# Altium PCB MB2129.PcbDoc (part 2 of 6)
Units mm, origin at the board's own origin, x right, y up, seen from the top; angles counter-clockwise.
Board outline 70 x 133.34 mm, 6 copper layers (Top Layer, Signal Layer 1, Signal Layer 2, Signal Layer 3, Signal Layer 4, Bottom Layer), stack 1.57 mm thick; 377 components, 289 nets, 1482 pads, 1373 vias.
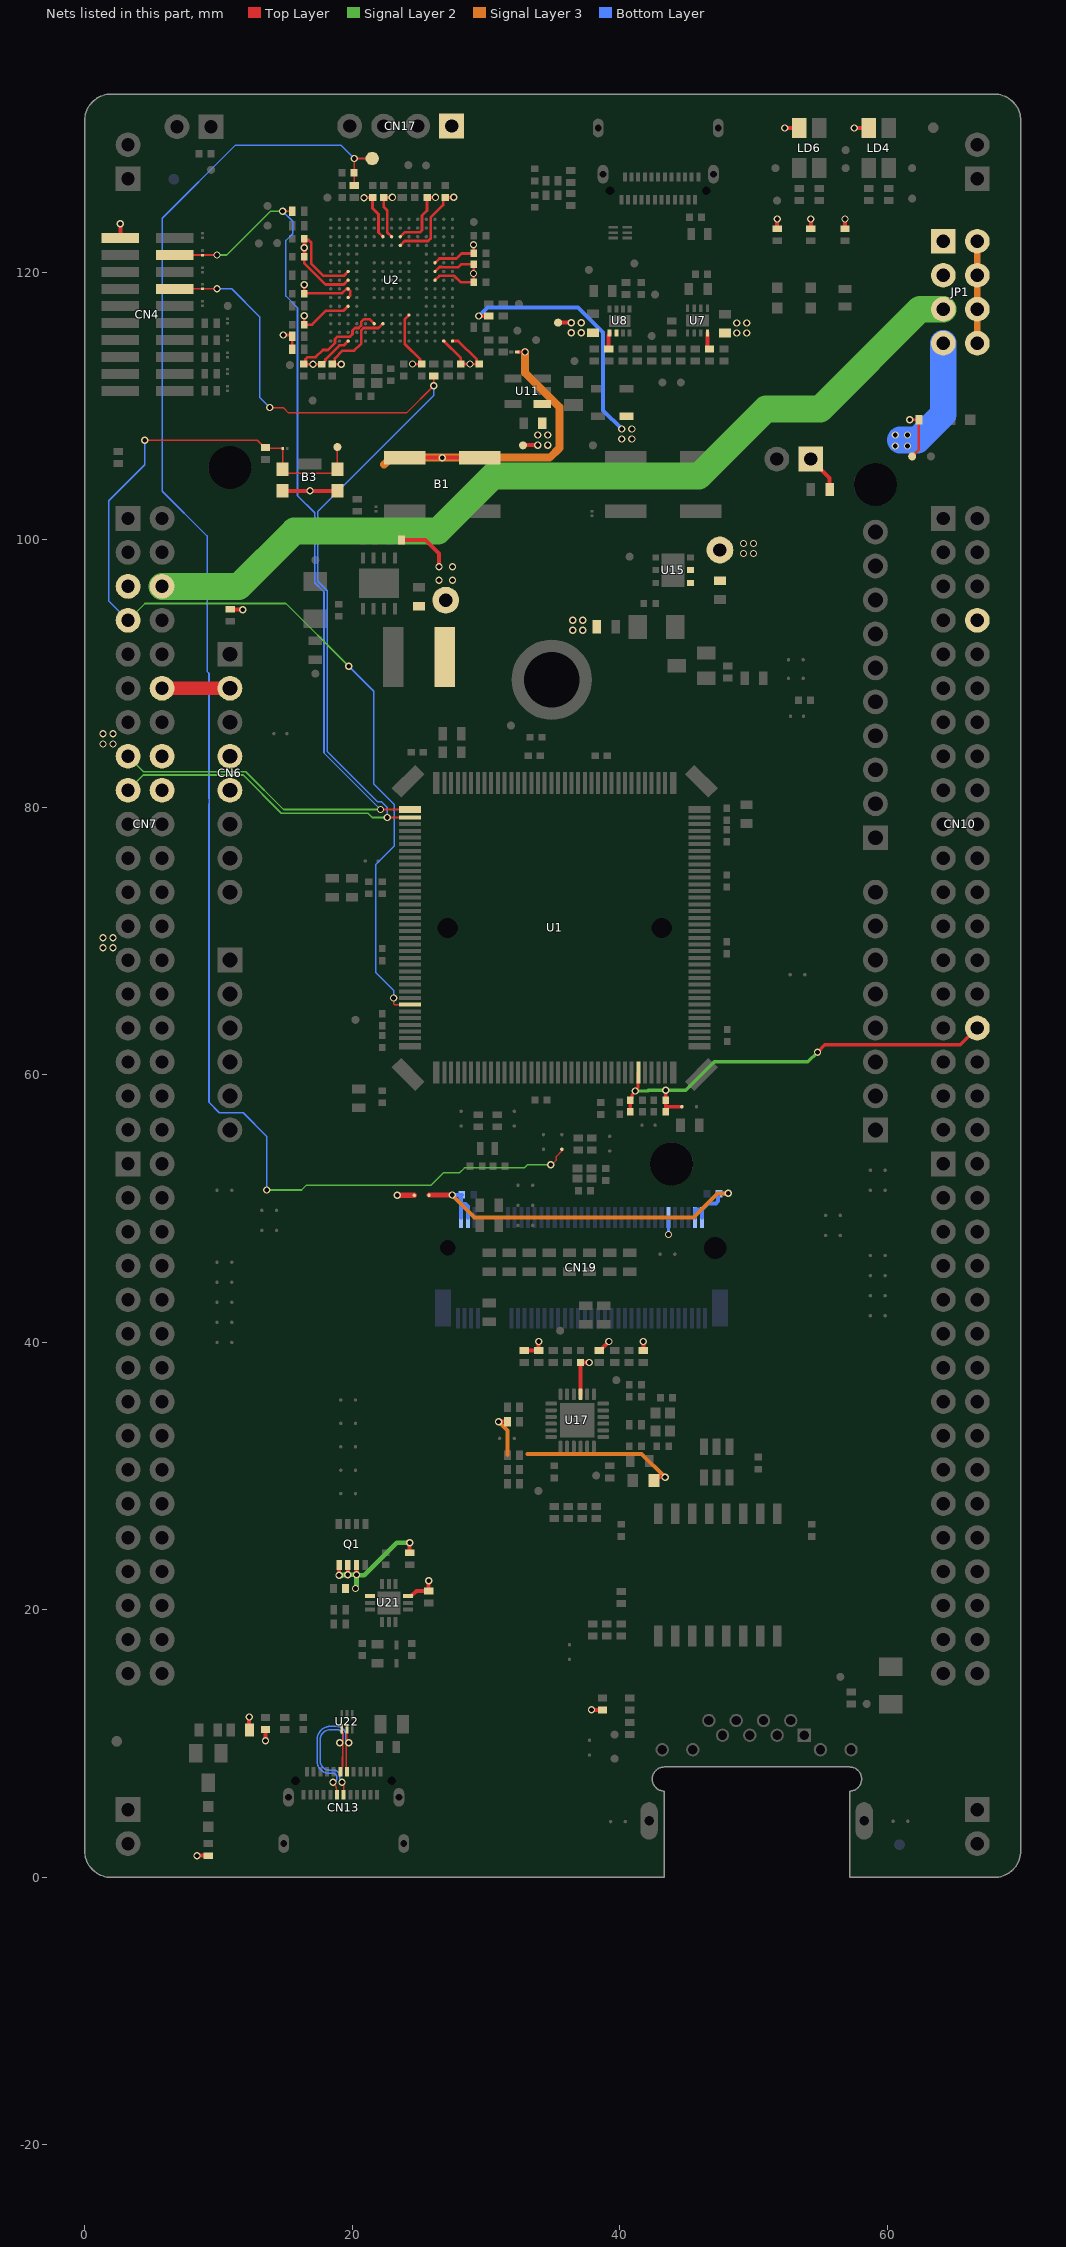
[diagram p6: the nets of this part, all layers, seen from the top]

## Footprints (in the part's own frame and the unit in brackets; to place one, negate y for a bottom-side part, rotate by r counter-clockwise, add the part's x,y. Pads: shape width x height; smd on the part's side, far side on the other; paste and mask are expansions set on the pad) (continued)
CON_SAMTEC_TSW-119-09-X-D [mm]
  rect 1.85x1.85 / inner round 1.85 / far side rect 1.85x1.85 hole 1 mask+0.05: 1(-22.86,-1.27)
  round 1.85 hole 1 mask+0.05: 2(-22.86,1.27) 3(-20.32,-1.27) 4(-20.32,1.27) 5(-17.78,-1.27) 6(-17.78,1.27) 7(-15.24,-1.27) 8(-15.24,1.27) 9(-12.7,-1.27) 10(-12.7,1.27) 11(-10.16,-1.27) 12(-10.16,1.27) 13(-7.62,-1.27) 14(-7.62,1.27) 15(-5.08,-1.27) 16(-5.08,1.27) 17(-2.54,-1.27) 18(-2.54,1.27) 19(0,-1.27) 20(0,1.27) 21(2.54,-1.27) 22(2.54,1.27) 23(5.08,-1.27) 24(5.08,1.27) 25(7.62,-1.27) 26(7.62,1.27) 27(10.16,-1.27) 28(10.16,1.27) 29(12.7,-1.27) 30(12.7,1.27) 31(15.24,-1.27) 32(15.24,1.27) 33(17.78,-1.27) 34(17.78,1.27) 35(20.32,-1.27) 36(20.32,1.27) 37(22.86,-1.27) 38(22.86,1.27)
  silkscreen extent -24.13,-2.54 24.13,2.54, body extent -24.13,-2.55 24.13,2.54, height 8.38
CON_USB-TYPEC_AMPHENOL_12401826E412A [mm] "MCD-03232"
  round 0 hole 0.65 unplated mask+0.05: 0(-3.6,0)
  round 0 hole 0.65 slot 0.95 at 0 deg unplated mask+0.05: 0(3.6,0)
  rect 0.3x0.7 smd mask+0.05: A1(-2.75,0.66) A2(-2.25,0.66) A3(-1.75,0.66) A4(-1.25,0.66) A5(-0.75,0.66) A6(-0.25,0.66) A7(0.25,0.66) A8(0.75,0.66) A9(1.25,0.66) A10(1.75,0.66) A11(2.25,0.66) A12(2.75,0.66) B1(2.5,-1.04) B2(2,-1.04) B3(1.5,-1.04) B4(1,-1.04) B5(0.5,-1.04) B6(0,-1.04) B7(-0.5,-1.04) B8(-1,-1.04) B9(-1.5,-1.04) B10(-2,-1.04) B11(-2.5,-1.04) B12(-3,-1.04)
  oval 0.8x1.4 hole 0.5 slot 1.1 at 90 deg mask+0.05: SH1(-4.13,-1.25) SH2(4.13,-1.25) SH3(-4.49,-4.7) SH4(4.49,-4.7)
  Top Layer keep-out region: -3.75,-7.24 3.75,-7.24 3.75,-1.95 -3.75,-1.95
  silkscreen extent -4.7,-9.59 4.7,0.91, body extent -4.6,-9.59 4.6,0.91, height 3.26
CRY_NX1610SE_2P [mm] "MCD-02291"
  rect 0.5x1 smd mask+0.05: 1(-0.55,0) 2(0.55,0)
  silkscreen extent -0.13,-0.5 0.13,0.5, body extent -0.8,-0.5 0.8,0.5, height 0.45
CRY_NX1612SA_4P [mm] "MCD-02262"
  rect 0.75x0.6 smd mask+0.038: 1(-0.525,-0.375) 2(0.525,-0.375) 3(0.525,0.375) 4(-0.525,0.375)
  silkscreen extent -1.02,-0.8 0.03,0.6, body extent -0.8,-0.6 0.8,0.6, height 0.31
CRY_NX2016SA_4P [mm]
  rect 0.85x0.75 smd mask+0.05: 1(-0.675,-0.525) 2(0.675,-0.525) 3(0.675,0.525) 4(-0.675,0.525)
  silkscreen extent -1.22,-1.02 1.05,0.85, body extent -1.05,-0.85 1.05,0.85, height 0.7
DIO_SOD323_1A_2K [mm]
  rect 1.06x0.54 smd mask+0.05: 1(-1.07,0) 2(1.07,0)
  silkscreen extent -0.9,-0.72 0.9,0.72, body extent -1.3,-0.78 1.3,0.78, height 1.17
DIO_SOD523_1A_2K [mm] "MCD-01677"
  rect 0.65x0.3 smd mask+0.05: 1(-0.675,0) 2(0.675,0)
  silkscreen extent -0.65,-0.45 1.05,0.55, body extent -0.85,-0.45 0.85,0.45, height 0.71
ESD_0201_H0P3_1K_2A [mm] "MCD-03501"
  rect 0.187x0.225 smd paste-0.01 mask+0.025: 1(-0.169,0) 2(0.169,0)
  silkscreen extent -0.35,-0.15 -0.35,0.15, body extent -0.3,-0.17 0.3,0.17, height 0.3
ESD_QFN1610_2N_1K_2A [mm] "DFN, 2-Leads, Body 1.60x1.00mm"
  rect 0.55x0.9 smd mask+0.05: 1(-0.625,0) 2(0.625,0)
  silkscreen extent -1.02,-0.58 0.85,0.58, body extent -0.85,-0.55 0.85,0.55, height 0.6
ESD_SOT23-6L [mm]
  rect 0.6x1.2 smd mask+0.05: 1(-0.95,-1.15) 2(0,-1.15) 3(0.95,-1.15) 4(0.95,1.15) 5(0,1.15) 6(-0.95,1.15)
  silkscreen extent -1.53,-0.87 1.53,0.87, body extent -1.52,-1.5 1.52,1.5, height 1.45
ESD_UQFN-6L_1P45X1P4_P040 [mm] "MCD-03060"
  rect 0.2x0.7 smd mask+0.05: 1(-0.4,-0.525) 2(0,-0.525) 3(0.4,-0.525) 4(0.4,0.525) 5(0,0.525) 6(-0.4,0.525)
  body extent -0.72,-0.7 0.72,0.7, height 0.51
ICC_DFN6-EPAD_3X3_P095 [mm]
  rect 0.45x0.5 smd mask+0.05: 1(-0.95,-1.3) 2(0,-1.3) 3(0.95,-1.3) 4(0.95,1.3) 5(0,1.3) 6(-0.95,1.3)
  rect 2.5x1.7 smd mask+0.05: EP(0,0)
  silkscreen extent -1.55,-1.55 1.55,1.55, body extent -1.55,-1.55 1.55,1.55, height 1
ICC_DFN8-EPAD_2X2_P050_H0P8 [mm] "MCD-03814"
  rect 0.25x0.55 smd mask+0.05: 1(0.75,0.925) 2(0.25,0.925) 3(-0.25,0.925) 4(-0.75,0.925) 5(-0.75,-0.925) 6(-0.25,-0.925) 7(0.25,-0.925) 8(0.75,-0.925)
  rect 1.75x0.9 smd mask+0.05: 9(0,0)
  silkscreen extent -1.05,-1.05 1.25,1.35, body extent -1,-1.05 1,1.05, height 0.8
ICC_LQFP144_20X20_P050_SOCKET_YAMAICHI_IC149-144-145-B5_NM [mm]
  rect 1x2.5 smd rot 45 mask+0.05: 0(-10.96,-10.96) 0(10.96,10.96)
  rect 1x2.5 smd rot 135 mask+0.05: 0(-10.96,10.96) 0(10.96,-10.96)
  round 0 hole 1.5 unplated mask+0.05: 0(0,8) 0(0,-8)
  rect 1.65x0.5 smd mask+0.05: 1(-10.825,8.85) 36(-10.825,-8.85) 73(10.825,-8.85) 108(10.825,8.85)
  rect 1.65x0.3 smd mask+0.05: 2(-10.825,8.25) 3(-10.825,7.75) 4(-10.825,7.25) 5(-10.825,6.75) 6(-10.825,6.25) 7(-10.825,5.75) 8(-10.825,5.25) 9(-10.825,4.75) 10(-10.825,4.25) 11(-10.825,3.75) 12(-10.825,3.25) 13(-10.825,2.75) 14(-10.825,2.25) 15(-10.825,1.75) 16(-10.825,1.25) 17(-10.825,0.75) 18(-10.825,0.25) 19(-10.825,-0.25) 20(-10.825,-0.75) 21(-10.825,-1.25) 22(-10.825,-1.75) 23(-10.825,-2.25) 24(-10.825,-2.75) 25(-10.825,-3.25) 26(-10.825,-3.75) 27(-10.825,-4.25) 28(-10.825,-4.75) 29(-10.825,-5.25) 30(-10.825,-5.75) 31(-10.825,-6.25) 32(-10.825,-6.75) 33(-10.825,-7.25) 34(-10.825,-7.75) 35(-10.825,-8.25) 74(10.825,-8.25) 75(10.825,-7.75) 76(10.825,-7.25) 77(10.825,-6.75) 78(10.825,-6.25) 79(10.825,-5.75) 80(10.825,-5.25) 81(10.825,-4.75) 82(10.825,-4.25) 83(10.825,-3.75) 84(10.825,-3.25) 85(10.825,-2.75) 86(10.825,-2.25) 87(10.825,-1.75) 88(10.825,-1.25) 89(10.825,-0.75) 90(10.825,-0.25) 91(10.825,0.25) 92(10.825,0.75) 93(10.825,1.25) 94(10.825,1.75) 95(10.825,2.25) 96(10.825,2.75) 97(10.825,3.25) 98(10.825,3.75) 99(10.825,4.25) 100(10.825,4.75) 101(10.825,5.25) 102(10.825,5.75) 103(10.825,6.25) 104(10.825,6.75) 105(10.825,7.25) 106(10.825,7.75) 107(10.825,8.25)
  rect 0.5x1.65 smd mask+0.05: 37(-8.85,-10.825) 72(8.85,-10.825) 109(8.85,10.825) 144(-8.85,10.825)
  rect 0.3x1.65 smd mask+0.05: 38(-8.25,-10.825) 39(-7.75,-10.825) 40(-7.25,-10.825) 41(-6.75,-10.825) 42(-6.25,-10.825) 43(-5.75,-10.825) 44(-5.25,-10.825) 45(-4.75,-10.825) 46(-4.25,-10.825) 47(-3.75,-10.825) 48(-3.25,-10.825) 49(-2.75,-10.825) 50(-2.25,-10.825) 51(-1.75,-10.825) 52(-1.25,-10.825) 53(-0.75,-10.825) 54(-0.25,-10.825) 55(0.25,-10.825) 56(0.75,-10.825) 57(1.25,-10.825) 58(1.75,-10.825) 59(2.25,-10.825) 60(2.75,-10.825) 61(3.25,-10.825) 62(3.75,-10.825) 63(4.25,-10.825) 64(4.75,-10.825) 65(5.25,-10.825) 66(5.75,-10.825) 67(6.25,-10.825) 68(6.75,-10.825) 69(7.25,-10.825) 70(7.75,-10.825) 71(8.25,-10.825) 110(8.25,10.825) 111(7.75,10.825) 112(7.25,10.825) 113(6.75,10.825) 114(6.25,10.825) 115(5.75,10.825) 116(5.25,10.825) 117(4.75,10.825) 118(4.25,10.825) 119(3.75,10.825) 120(3.25,10.825) 121(2.75,10.825) 122(2.25,10.825) 123(1.75,10.825) 124(1.25,10.825) 125(0.75,10.825) 126(0.25,10.825) 127(-0.25,10.825) 128(-0.75,10.825) 129(-1.25,10.825) 130(-1.75,10.825) 131(-2.25,10.825) 132(-2.75,10.825) 133(-3.25,10.825) 134(-3.75,10.825) 135(-4.25,10.825) 136(-4.75,10.825) 137(-5.25,10.825) 138(-5.75,10.825) 139(-6.25,10.825) 140(-6.75,10.825) 141(-7.25,10.825) 142(-7.75,10.825) 143(-8.25,10.825)
  silkscreen extent -10.1,-10.1 10.1,10.1, body extent -11,-11 11,11, height 1.6
ICC_QFN12L-EPAD_3X3_P050 [mm] "MCD-01809"
  rect 0.3x0.75 smd mask+0.05: 1(-0.5,-1.425) 2(0,-1.425) 3(0.5,-1.425) 7(0.5,1.425) 8(0,1.425) 9(-0.5,1.425)
  rect 0.75x0.3 smd mask+0.05: 4(1.425,-0.5) 5(1.425,0) 6(1.425,0.5) 10(-1.425,0.5) 11(-1.425,0) 12(-1.425,-0.5)
  rect 1.7x1.7 smd mask+0.05: 13(0,0)
  body extent -1.55,-1.55 1.55,1.55, height 0.8
ICC_SOT23-3L_H1P12 [mm]
  rect 1x1.4 smd mask+0.05: 1(-0.95,-1.1) 2(0.95,-1.1) 3(0,1.1)
  silkscreen extent -1.63,-0.82 1.63,0.82, body extent -1.56,-1.25 1.56,1.25, height 1.12
ICC_SOT23-5L_H1P45 [mm]
  rect 0.6x1.3 smd mask+0.05: 1(-0.95,-1.1) 2(0,-1.1) 3(0.95,-1.1) 4(0.95,1.1) 5(-0.95,1.1)
  silkscreen extent -1.75,-1.68 1.6,0.97, body extent -1.52,-1.25 1.52,1.25, height 1.45
ICC_UFBGA201_176+25_10X10_P065 [mm] "IPC"
  round 0.25 smd mask+0.038: A1(-4.55,4.55) A2(-3.9,4.55) A3(-3.25,4.55) A4(-2.6,4.55) A5(-1.95,4.55) A6(-1.3,4.55) A7(-0.65,4.55) A8(0,4.55) A9(0.65,4.55) A10(1.3,4.55) A11(1.95,4.55) A12(2.6,4.55) A13(3.25,4.55) A14(3.9,4.55) A15(4.55,4.55) B1(-4.55,3.9) B2(-3.9,3.9) B3(-3.25,3.9) B4(-2.6,3.9) B5(-1.95,3.9) B6(-1.3,3.9) B7(-0.65,3.9) B8(0,3.9) B9(0.65,3.9) B10(1.3,3.9) B11(1.95,3.9) B12(2.6,3.9) B13(3.25,3.9) B14(3.9,3.9) B15(4.55,3.9) C1(-4.55,3.25) C2(-3.9,3.25) C3(-3.25,3.25) C4(-2.6,3.25) C5(-1.95,3.25) C6(-1.3,3.25) C7(-0.65,3.25) C8(0,3.25) C9(0.65,3.25) C10(1.3,3.25) C11(1.95,3.25) C12(2.6,3.25) C13(3.25,3.25) C14(3.9,3.25) C15(4.55,3.25) D1(-4.55,2.6) D2(-3.9,2.6) D3(-3.25,2.6) D4(-2.6,2.6) D5(-1.95,2.6) D6(-1.3,2.6) D7(-0.65,2.6) D8(0,2.6) D9(0.65,2.6) D10(1.3,2.6) D11(1.95,2.6) D12(2.6,2.6) D13(3.25,2.6) D14(3.9,2.6) D15(4.55,2.6) E1(-4.55,1.95) E2(-3.9,1.95) E3(-3.25,1.95) E4(-2.6,1.95) E12(2.6,1.95) E13(3.25,1.95) E14(3.9,1.95) E15(4.55,1.95) F1(-4.55,1.3) F2(-3.9,1.3) F3(-3.25,1.3) F4(-2.6,1.3) F6(-1.3,1.3) F7(-0.65,1.3) F8(0,1.3) F9(0.65,1.3) F10(1.3,1.3) F12(2.6,1.3) F13(3.25,1.3) F14(3.9,1.3) F15(4.55,1.3) G1(-4.55,0.65) G2(-3.9,0.65) G3(-3.25,0.65) G4(-2.6,0.65) G6(-1.3,0.65) G7(-0.65,0.65) G8(0,0.65) G9(0.65,0.65) G10(1.3,0.65) G12(2.6,0.65) G13(3.25,0.65) G14(3.9,0.65) G15(4.55,0.65) H1(-4.55,0) H2(-3.9,0) H3(-3.25,0) H4(-2.6,0) H6(-1.3,0) H7(-0.65,0) H8(0,0) H9(0.65,0) H10(1.3,0) H12(2.6,0) H13(3.25,0) H14(3.9,0) H15(4.55,0) J1(-4.55,-0.65) J2(-3.9,-0.65) J3(-3.25,-0.65) J4(-2.6,-0.65) J6(-1.3,-0.65) J7(-0.65,-0.65) J8(0,-0.65) J9(0.65,-0.65) J10(1.3,-0.65) J12(2.6,-0.65) J13(3.25,-0.65) J14(3.9,-0.65) J15(4.55,-0.65) K1(-4.55,-1.3) K2(-3.9,-1.3) K3(-3.25,-1.3) K4(-2.6,-1.3) K6(-1.3,-1.3) K7(-0.65,-1.3) K8(0,-1.3) K9(0.65,-1.3) K10(1.3,-1.3) K12(2.6,-1.3) K13(3.25,-1.3) K14(3.9,-1.3) K15(4.55,-1.3) L1(-4.55,-1.95) L2(-3.9,-1.95) L3(-3.25,-1.95) L4(-2.6,-1.95) L12(2.6,-1.95) L13(3.25,-1.95) L14(3.9,-1.95) L15(4.55,-1.95) M1(-4.55,-2.6) M2(-3.9,-2.6) M3(-3.25,-2.6) M4(-2.6,-2.6) M5(-1.95,-2.6) M6(-1.3,-2.6) M7(-0.65,-2.6) M8(0,-2.6) M9(0.65,-2.6) M10(1.3,-2.6) M11(1.95,-2.6) M12(2.6,-2.6) M13(3.25,-2.6) M14(3.9,-2.6) M15(4.55,-2.6) N1(-4.55,-3.25) N2(-3.9,-3.25) N3(-3.25,-3.25) N4(-2.6,-3.25) N5(-1.95,-3.25) N6(-1.3,-3.25) N7(-0.65,-3.25) N8(0,-3.25) N9(0.65,-3.25) N10(1.3,-3.25) N11(1.95,-3.25) N12(2.6,-3.25) N13(3.25,-3.25) N14(3.9,-3.25) N15(4.55,-3.25) P1(-4.55,-3.9) P2(-3.9,-3.9) P3(-3.25,-3.9) P4(-2.6,-3.9) P5(-1.95,-3.9) P6(-1.3,-3.9) P7(-0.65,-3.9) P8(0,-3.9) P9(0.65,-3.9) P10(1.3,-3.9) P11(1.95,-3.9) P12(2.6,-3.9) P13(3.25,-3.9) P14(3.9,-3.9) P15(4.55,-3.9) R1(-4.55,-4.55) R2(-3.9,-4.55) R3(-3.25,-4.55) R4(-2.6,-4.55) R5(-1.95,-4.55) R6(-1.3,-4.55) R7(-0.65,-4.55) R8(0,-4.55) R9(0.65,-4.55) R10(1.3,-4.55) R11(1.95,-4.55) R12(2.6,-4.55) R13(3.25,-4.55) R14(3.9,-4.55) R15(4.55,-4.55)
  silkscreen extent -5.22,-5.07 5.07,5.23, body extent -5.07,-5.07 5.07,5.07, height 0.61
ICC_VFQFPN8-EPAD_4X4_P080 [mm] "MCD-02219"
  rect 0.3x0.85 smd mask+0.05: 1(-1.2,-1.9) 2(-0.4,-1.9) 3(0.4,-1.9) 4(1.2,-1.9) 5(1.2,1.9) 6(0.4,1.9) 7(-0.4,1.9) 8(-1.2,1.9)
  rect 3x2.2 smd mask+0.05: 9(0,0)
  silkscreen extent -2,-2 2,2, body extent -2,-2 2,2, height 1.1
ICC_VQFN24-EPAD_4X4_P050 [mm]
  rrect50% 0.85x0.3 smd mask+0.05: 1(-1.95,1.25) 2(-1.95,0.75) 3(-1.95,0.25) 4(-1.95,-0.25) 5(-1.95,-0.75) 6(-1.95,-1.25) 13(1.95,-1.25) 14(1.95,-0.75) 15(1.95,-0.25) 16(1.95,0.25) 17(1.95,0.75) 18(1.95,1.25)
  rrect50% 0.3x0.85 smd mask+0.05: 7(-1.25,-1.95) 8(-0.75,-1.95) 9(-0.25,-1.95) 10(0.25,-1.95) 11(0.75,-1.95) 12(1.25,-1.95) 19(1.25,1.95) 20(0.75,1.95) 21(0.25,1.95) 22(-0.25,1.95) 23(-0.75,1.95) 24(-1.25,1.95)
  rect 2.6x2.6 smd paste-10 mask+0.05: EP(0,0)
  silkscreen extent -2,-2 2,2, body extent -2.05,-2.05 2.05,2.05, height 1.1
ICC_WSON8-EPAD_2X2_P050 [mm] "MCD-02194"
  rect 0.5x0.3 smd paste+0 mask+0.05: 1(-0.9,0.75) 2(-0.9,0.25) 3(-0.9,-0.25) 4(-0.9,-0.75) 5(0.9,-0.75) 6(0.9,-0.25) 7(0.9,0.25) 8(0.9,0.75)
  rect 0.9x1.6 smd paste+0 mask+0.05: 9(0,0)
  silkscreen extent -0.5,-1 0.5,1, body extent -1,-1 1,1, height 0.81
IND_5040_WURTH_74404054033 [mm] "MCD-02220"
  rect 1.55x4.5 smd mask+0.05: 1(1.925,0) 2(-1.925,0)
  silkscreen extent -1.5,-2.5 1.5,2.5, body extent -2.6,-2.5 2.6,2.5, height 4
L0603 [mm]
  rect 0.8x0.95 smd mask+0.05: 1(-0.8,0) 2(0.8,0)
  silkscreen extent -1.33,-0.6 1.33,0.6, body extent -0.87,-0.47 0.87,0.47, height 0.95
LED_0603_OSRAM_LG-Q396-PS-35_GREEN_1A2K_H0P4 [mm]
  rect 0.8x0.8 smd mask+0.05: 1(-0.75,0) 2(0.75,0)
  silkscreen extent -0.85,-0.53 1.28,0.53, body extent -0.85,-0.45 0.85,0.45, height 0.6
LED_0603_RED [mm]
  rect 0.8x0.8 smd mask+0.05: 1(-0.75,0) 2(0.75,0)
  silkscreen extent -0.25,-0.4 1.25,0.4, body extent -0.8,-0.4 0.8,0.4, height 0.6
LED_0603_SMD-B_BLUE_H0P4 [mm]
  rect 0.6x1 smd mask+0.05: 1(-0.65,0) 2(0.65,0)
  silkscreen extent -0.23,-0.45 1.07,0.45, body extent -0.85,-0.45 0.85,0.45, height 0.5
LED_BI-GR_WE-150141SV73110 [mm] "MCD-02631"
  rect 1.1x1.5 smd mask+0.05: 1(-0.75,1.5) 2(0.75,1.5) 3(-0.75,-1.5) 4(0.75,-1.5)
  silkscreen extent -1.65,-1.85 1.5,1.7, body extent -1.5,-1.85 1.5,1.85, height 2.1
LINK200 [mm]
  rect 0.2x0.35 smd paste-10 mask+0.05: 1(0,-0.225) 2(0,0.225)
MIRE_PLACE_SMD_0P8MM [mm]
  round 0.8 smd paste-10 mask+0.2: 1(0,0)
  Top Layer keep-out circle w0.01: c0,0 r0.804
MISC_REGO_S001_00001_A42_R [mm] "MCD-03863"
  round 6 hole 4.15 mask+0.05: 1(0,0)
  silkscreen extent -3.27,-3.27 3.27,3.27, body extent -2.8,-2.8 2.8,2.8, height 2.5
MOS_POWERFLAT_3P3X3P3_P065 [mm] "MCD-01126"
  rect 0.4x0.75 smd mask+0.05: 1(-0.975,-1.525) 2(-0.325,-1.525) 3(0.325,-1.525) 4(0.975,-1.525) 6(0.325,1.525) 7(-0.325,1.525)
  rect 0.45x0.75 smd mask+0.05: 5(1,1.525) 8(-1,1.525)
  Top Layer region: -1.755,0.2 -1.755,-0.2 -1.225,-0.2 -1.225,-0.5 1.225,-0.5 1.225,-0.2 1.755,-0.2 1.755,0.2 1.225,0.2 1.225,1.9 -1.225,1.9 -1.225,0.2
  silkscreen extent -1.63,-1.55 1.63,1.55, body extent -1.75,-1.75 1.75,1.75, height 0.91
NPN_SOT23 [mm]
  rect 1x1.4 smd mask+0.05: 1(-0.95,-1.1) 2(0.95,-1.1) 3(0,1.1)
  silkscreen extent -1.63,-0.82 1.63,0.82, body extent -1.56,-1.25 1.56,1.25, height 1.1
R0402 [mm]
  rect 0.51x0.7 smd mask+0.05: 1(-0.45,0) 2(0.45,0)
  body extent -0.52,-0.3 0.52,0.3, height 0.4
R0603 [mm]
  rect 0.64x1 smd mask+0.05: 1(-0.7,0) 2(0.7,0)
  silkscreen extent -1.05,-0.58 1.05,0.58, body extent -0.9,-0.5 0.9,0.5, height 0.56
SOLDER-BRIDGE_R0402-0R [mil] "MCD-01619"
  round 10 smd paste-393.7: 1(-17.72,0) 2(20.67,0)
  Top Layer region: -30.51,-13.78 -30.51,13.78 -8.86,13.78 -2.95,0 -8.86,-13.78
  Top Layer region: 1.48,13.78 8.37,0 1.48,-13.78 30.51,-13.78 30.51,13.78
  silkscreen extent -33,-17 33,17, body extent -20,-12 20,12, height 14
SOLDER-BRIDGE_R0603-0R [mil]
  round 10 smd paste-393.7: 1(-19.68,0) 2(23.62,0)
  Top Layer region: -3.94,19.69 15.75,0 -3.94,-19.68 47.24,-19.68 47.24,19.69
  Top Layer region: -47.24,-19.68 -47.24,19.69 -17.72,19.69 1.97,0 -17.72,-19.68
  silkscreen extent -50,-23 50,23, body extent -36,-20 36,20, height 22
STICKER_PRODUCT_25X9 [mm] "Sticker to mention board CPN code"
  silkscreen extent -12.5,-4.5 12.5,4.5
SWI_C&K_KSC321JLFS_BLACK [mm] "MCD-01799"
  rect 3.1x1 smd mask+0.05: 1(-2.8,2) 2(2.8,2) 3(-2.8,-2) 4(2.8,-2)
  silkscreen extent -3.25,-3.25 3.25,3.25, body extent -3.4,-3.25 3.4,3.25, height 3.5
SWI_C&K_KSC721JLFS_BLUE [mm] "MCD-01800"
  rect 3.1x1 smd mask+0.05: 1(-2.8,2) 2(2.8,2) 3(-2.8,-2) 4(2.8,-2)
  silkscreen extent -3.25,-3.25 3.25,3.25, body extent -3.4,-3.25 3.4,3.25, height 4.3
SWI_C&K_Y78B23110FP__ITT_KMR231GLFS [mm] "MCD-00715"
  rect 0.9x1 smd mask+0.05: 1(2.05,0.8) 2(2.05,-0.8) 3(-2.05,0.8) 4(-2.05,-0.8)
  rect 1.7x0.8 smd mask+0.05: 5(0,1.2)
  silkscreen extent -2.05,-1.43 2.05,1.43, body extent -2.3,-1.5 2.3,1.5, height 2.1
TP_PTH_1MM_2MM [mm] "MCD-01506"
  round 2 hole 1 mask+0.05: 1(0,0)
  silkscreen extent -1.2,-1.2 1.2,1.2
TP_SMD_0-6MM [mm]
  round 0.6 smd paste-10 mask+0.05: 1(0,0)
  silkscreen extent -0.5,-0.5 0.5,0.5
TP_SMD_1MM [mm]
  round 1 smd paste-10 mask+0.05: 1(0,0)
  silkscreen extent -0.7,-0.7 0.7,0.7
TRS_DGKYD_KMS-1102NL [mm]
  rect 0.64x1.55 smd mask+0.05: 1(-4.445,-4.575) 2(-3.175,-4.575) 3(-1.905,-4.575) 4(-0.635,-4.575) 5(0.635,-4.575) 6(1.905,-4.575) 7(3.175,-4.575) 8(4.445,-4.575) 9(4.445,4.575) 10(3.175,4.575) 11(1.905,4.575) 12(0.635,4.575) 13(-0.635,4.575) 14(-1.905,4.575) 15(-3.175,4.575) 16(-4.445,4.575)
  silkscreen extent -6.35,-3.7 6.35,3.7, body extent -6.35,-4.7 6.35,4.7, height 6.3

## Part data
B1: library part MCD-01800, "Switch tactile, SPST-NO, 32V, 50mA, 6.2x6.2mm", Manufacturer=C&K, Manufacturer_HQ_COO=Unknown, Manufacturer_Part_Number=KSC721JLFS, Package=6.2x6.2mm
B2: library part MCD-01799, "Switch tactile, SPST-NO, 32V, 50mA, 6.2x6.2mm", Manufacturer=C&K, Manufacturer_HQ_COO=Unknown, Manufacturer_Part_Number=KSC321JLFS, Package=6.2x6.2mm
B3: library part MCD-01485, "Switch tactile, SPST-NO, 32V, 50mA, 2.8x4.6mm", Manufacturer=C&K, Manufacturer_HQ_COO=Unknown, Manufacturer_Part_Number=KMR231GLFS, Package=2.8x4.6mm
C1 C5 C6 C8 C9 C13 C14 C15 C16 C18 C22 C25 C26 C27 C29 C30 C31 C32 C43 C44 C47 C69 C70 C73 C84 C88 C90 C92 C94 C95: library part MCD-00006, "Capacitor, MLCC, 100nF, 16V, X7R, +/-10%, 0402, T=0.5mm", Manufacturer=YAGEO, Manufacturer_Part_Number=CC0402KRX7R7BB104, Package=0402
C2 C10 C19 C28 C96: library part MCD-02198, "Capacitor, MLCC, 10nF, 50V, X7R, +/-10%, 0402, T=0.5mm", Manufacturer=YAGEO, Manufacturer_Part_Number=CC0402KRX7R9BB103, Package=0402
C3: library part MCD-00016, "Capacitor, MLCC, 20pF, 50V, NPO, +/- 5%, 0402, T=0.5mm", Manufacturer=YAGEO, Manufacturer_Part_Number=CC0402JRNPO9BN200, Package=0402
C4 C7 C12: library part MCD-02606, "Capacitor, MLCC, 2.2uF, 6.3V, X5R, +/-10%, 0402, T=0.5mm", Manufacturer=YAGEO, Manufacturer_Part_Number=CC0402KRX5R5BB225, Package=0402
C11: library part MCD-00205, "Capacitor, MLCC, 100pF, 50V, NPO, +/-5%, 0402, T=0.5mm", Manufacturer=YAGEO, Manufacturer_Part_Number=CC0402JRNPO9BN101, Package=0402
C17: library part MCD-00095, "Capacitor, MLCC, 1uF, 25V, X5R, +/-10%, 0402, T=0.5mm", Manufacturer=MURATA, Manufacturer_Part_Number=GRM155R61E105KA12, Package=0402
C20 C21 C99: library part MCD-01099, "Capacitor, MLCC, 100nF, 50V, X7R, +/-10%, 0603, T=0.8mm", Manufacturer=YAGEO, Manufacturer_Part_Number=CC0603KRX7R9BB104, Package=0603
C23 C24 C36 C91: library part MCD-00099, "Capacitor, MLCC, 10uF, 10V, X5R, +/-10%, 0603, T=0.8mm", Manufacturer=MURATA, Manufacturer_Part_Number=GRM188R61A106KE69D, Package=0603
C33 C35 C87 C89: library part MCD-01374, "Capacitor, MLCC, 5.6pF, 50V, NPO, +/-0.1pF, 0402, T=0.5mm", Manufacturer=YAGEO, Manufacturer_Part_Number=CC0402BRNPO9BN5R6, Package=0402
C34: library part MCD-02372, "Capacitor, MLCC, 2.2uF, 25V, X7R, +/-10%, 0805, T=1,25mm", Manufacturer=MURATA, Manufacturer_Part_Number=GRM21BR71E225KE11L, Package=0805
C37 C38: library part MCD-02607, "Capacitor, MLCC, 22uF, 10V, X5R, +/-20%, 0603, T=0.8mm", Manufacturer=YAGEO, Manufacturer_Part_Number=CC0603MRX5R6BB226, Package=0603
C45 C46: library part MCD-02610, "Capacitor, MLCC, 10uF, 25V, X5R, +/-10%, 1206, T=1.6mm", Manufacturer=YAGEO, Manufacturer_Part_Number=CC1206KKX5R8BB106, Package=1206
C48 C49 C59: library part MCD-03342, "Capacitor, MLCC, 4.7uF, 10V, X5R, +/-20%, 0603, T=0.8mm", Manufacturer=YAGEO, Manufacturer_Part_Number=CC0603MRX5R6BB475, Package=0603
C50 C55 C68 C76 C77 C85 C106 C107: library part MCD-01722, "Capacitor, MLCC, 1uF, 10V, X5R, +/-10%, 0402, T=0.5mm", Manufacturer=YAGEO, Manufacturer_Part_Number=CC0402KRX5R6BB105, Package=0402
C51 C52 C53 C54 C57 C60 C65 C66 C67 C71 C72 C74: library part MCD-04435, "Capacitor, MLCC, 100nF, 10V, X5R, +/-10%, 0402, T=0.5mm", Manufacturer=MURATA, Manufacturer_Part_Number=GRM155R61A104KA01, Package=0402
C61 C64: library part MCD-04261, "Capacitor, MLCC, 2.2uF, 10V, X5R, +/-10%, 0402, T=0.5mm", Manufacturer=YAGEO, Manufacturer_Part_Number=CC0402KPX5R6BB225, Package=0402
C79 C81: library part MCD-01781, "Capacitor, MLCC, 6.8pF, 50V, C0G/NP0, +/-0.1pF, 0402, T=0.5mm", Manufacturer=YAGEO, Manufacturer_Part_Number=CC0402BRNPO9BN6R8, Package=0402
C82 C83: library part MCD-01775, "Capacitor, MLCC, 3.3pF, 50V, NPO, +/-0.1pF, 0402, T=0.5mm", Manufacturer=YAGEO, Manufacturer_Part_Number=CC0402BRNPO9BN3R3, Package=0402
C86: library part MCD-00724, "Capacitor, MLCC, 470pF, 50V, NPO, +/-5%, 0402, T=0.5mm", Manufacturer=YAGEO, Manufacturer_Part_Number=CC0402JRNPO9BN471, Package=0402
C97 C98: library part MCD-01579, "Capacitor, MLCC, 330pF, 50V, NPO, +/-5%, 0402, T=0.5mm", Manufacturer=YAGEO, Manufacturer_Part_Number=CC0402JRNPO9BN331, Package=0402
C100: library part MCD-00722, "Capacitor, MLCC, 1nF, 2KV, X7R, +/-10%, 1206, T=1.25mm", Manufacturer=YAGEO, Manufacturer_Part_Number=CC1206KKX7RDBB102, Package=1206
C104: library part MCD-02372, "Capacitor, MLCC, 2.2uF, 25V, X7R, +/-10%, 0805, T=1,25mm", Manufacturer=MURATA, Manufacturer_Part_Number=GRM21BR71E225KE11L, Package=C0805
C105: library part MCD-00015, "Capacitor, MLCC, 10pF, 50V, NPO, +/-5%, 0402, T=0.5mm", Manufacturer=YAGEO, Manufacturer_Part_Number=CC0402JRNPO9BN100, Package=0402
CN1 CN13: library part MCD-03232, "USB_TypeC, 24 pins, RA, SMD, T=2.96mm", Manufacturer="AMPHENOL ICC", Manufacturer_Part_Number=12401826E412A
CN2 CN3 CN15 CN16: library part MCD-00214, "Header, 2x1, 2.54mm, VR, TH, T=5.84mm/10.16mm", Manufacturer=SAMTEC, Manufacturer_Part_Number=TSW-102-09-G-S
CN4: library part MCD-00557, "Header, 10x2, 1.27mm, VR, SMD, T=3.05mm", Manufacturer=SAMTEC, Manufacturer_Part_Number=FTSH-110-01-L-DV
CN5: library part MCD-02080, "Socket, 10x1, 2.54mm, VR, TH, T=8.51/2.64mm", Manufacturer=SAMTEC, Manufacturer_Part_Number=SSW-110-01-G-S
CN6 CN9: library part MCD-01743, "Socket, 8x1, 2.54mm, VR, TH, T=8.51/2.64mm", Manufacturer=SAMTEC, Manufacturer_Part_Number=SSW-108-01-G-S
CN7 CN10: library part MCD-00213, "Header, 19x2, 2.54mm, VR, TH, T=5.84mm/10.16mm", Manufacturer=SAMTEC, Manufacturer_Part_Number=TSW-119-09-G-D
CN8: library part MCD-02079, "Socket, 6x1, 2.54mm, VR, TH, T=8.51/2.64mm", Manufacturer=SAMTEC, Manufacturer_Part_Number=SSW-106-01-G-S
CN11 CN12: library part MCD-02536, "Header, 16x2, 2.54mm, VR, TH, T=5.84mm/8.38mm", Manufacturer=SAMTEC, Manufacturer_Part_Number=TSW-116-07-G-D, Package=TSW
CN14: library part MCD-00717, "Connector_RJ45, single port, with LEDS, T= 11.05mm", Manufacturer="DONGGUAN KEYOUDA ELECTRONIC TECHNOLOGY", Manufacturer_Part_Number=KRJ-CB4.2GYZNL
CN17: library part MCD-00029, "Header, 4x1, 2.54mm, VR, TH, T=5.84mm/2.54mm", Manufacturer=SAMTEC, Manufacturer_Part_Number=TSW-104-07-G-S
CN19: library part MCD-03856, "Socket_M2_NGFF, Gen3, 67pins, keyA, RA, SMD, 4.2mm, plating Gold Flash", Manufacturer="AMPHENOL CS", Manufacturer_Part_Number=MDT420A03001, Package=M2
D1 D2: library part MCD-03011, "Diode, Schottky, 0V54, 1A, 23V, SOD-323", Manufacturer=STMICROELECTRONICS, Manufacturer_Part_Number=BAT20JFILM, Package=SOD-323
D3: library part MCD-01677, "Diode, Schottky, 0V9, 100mA, 40V, SOD523", Manufacturer=STMICROELECTRONICS, Manufacturer_HQ_COO=EU, Manufacturer_Part_Number=BAT54KFILM, Package=SOD523
HW1: library part MCD-00547, "Sticker product 25x9 mm", Manufacturer=N/A
HW6: library part MCD-03863, "NGFF Standoff, Brass, For M2 connector 4.2mm, diameter 5.5 / 4 and screw M3x3.7", Manufacturer="REGO ELECTRONICS INC", Manufacturer_Part_Number=S001-00001-A42-R
HW10 HW11 HW12 HW13: library part MCD-03135, "Fiducial Pad, 0.8mm", Manufacturer=N/A, Manufacturer_HQ_COO=Unknown
JP1: library part MCD-01910, "Header, 4x2, 2.54mm, VR, TH, T=5.84mm/2.54mm", Manufacturer=SAMTEC, Manufacturer_Part_Number=TSW-104-07-G-D
JP3 JP5: library part MCD-00045, "Header, 2x1, 2.54mm, VR, TH, T=5.84mm/2.54mm", Manufacturer=SAMTEC, Manufacturer_Part_Number=TSW-102-07-G-S
L2: library part MCD-02220, "Inductor, 3.3uH, +/-30%, 3.4A, 24mR, 5040, T=4mm", Manufacturer="WURTH ELEKTRONIK", Manufacturer_Part_Number=74404054033, Package=5040
L4: library part MCD-02437, "Ferrite bead, 600R@100MHz, +/-25%, 500mA, 380mR, 0603, T=0.8mm", Manufacturer=MURATA, Manufacturer_Part_Number=BLM18AG601SN1D, Package=0603
LD1 LD5 LD7: library part MCD-02901, "LED, Green, 2V, 20mA, 0603", Manufacturer=EVERLIGHT, Manufacturer_Part_Number=19-217/G7C-AN1P2/6T, Package=0603
LD2: library part MCD-02899, "LED, Red, 2V35, 20mA, 0603", Manufacturer=EVERLIGHT, Manufacturer_Part_Number=19-213/R6C-AP1Q2B/5T, Package=0603
LD3: library part MCD-02786, "LED, Blue, 2.5V to 3.1V, 10mA, 0603", Manufacturer=EVERLIGHT, Manufacturer_Part_Number=19-217/BHC-ZL1M2RY/6T, Package=0603
LD4: library part MCD-02631, "LED Bicolor, Red/Green, 2V, 20mA, 4-PLCC", Manufacturer="WURTH ELEKTRONIK", Manufacturer_Part_Number=150141SV73110, Package=4-PLCC
LD6: library part MCD-02631, "LED Bicolor, Green/Red, 2V, 20mA, 4-PLCC", Manufacturer="WURTH ELEKTRONIK", Manufacturer_Part_Number=150141SV73110, Package=4-PLCC
LNK1: library part MCD-02777, "Track link on PCB 200um width for layout routing", Manufacturer=N/A
Q1: library part MCD-01810, "Transistor, MOSFET, N-CH, 30V, 11A, PowerFLAT-8", Manufacturer=STMICROELECTRONICS, Manufacturer_HQ_COO=EU, Package=PowerFLAT-8
Q2: library part MCD-00073, "NPN Bipolar Transistor", Manufacturer="ON SEMICONDUCTOR", Manufacturer_Part_Number=BSR14, Package=SOT23
R1 R2 R3 R4 R16 R22 R26 R27 R29 R43 R46 R47 R50 R79 R97: library part MCD-00052, "Resistor, 0R, 0402, +/-5%, 1/16W", Manufacturer=YAGEO, Manufacturer_Part_Number=RC0402JR-070RL, Package=0402
R5 R14 R23: library part MCD-00333, "Resistor, 5K1, 0402, +/-1%, 1/16W", Manufacturer=YAGEO, Manufacturer_Part_Number=RC0402FR-075K1L, Package=0402
R6 R13 R21 R25 R101 R112: library part MCD-00059, "Resistor, 100K, 0402, +/-1%, 1/16W", Manufacturer=YAGEO, Manufacturer_Part_Number=RC0402FR-07100KL, Package=0402
R7: library part MCD-00067, "Resistor, 100R, 0402, +/- 1%, 1/16W", Manufacturer=YAGEO, Manufacturer_Part_Number=RC0402FR-07100RL, Package=0402
R8 R40 R42: library part MCD-00185, "Resistor, 3K, 0402, +/-1%, 1/16W", Manufacturer=YAGEO, Manufacturer_Part_Number=RC0402FR-073KL, Package=0402
R9 R11 R19: library part MCD-00062, "Resistor, 330R, 0402, +/-1%, 1/16W", Manufacturer=YAGEO, Manufacturer_Part_Number=RC0402FR-07330RL, Package=0402
R10 R12 R59: library part MCD-00061, "Resistor, 1K, 0402, +/-1%,1/16W", Manufacturer=YAGEO, Manufacturer_Part_Number=RC0402FR-071KL, Package=0402
R15 R20 R44 R45 R71 R74 R75 R77 R80 R82 R83: library part MCD-00455, "Resistor, 33R, 0402, +/-1%, 1/16W", Manufacturer=YAGEO, Manufacturer_Part_Number=RC0402FR-0733RL, Package=0402
R17 R18 R105: library part MCD-00064, "Resistor, 510R, 0402, +/-1%, 1/16W", Manufacturer=YAGEO, Manufacturer_Part_Number=RC0402FR-07510RL, Package=0402
R24 R28 R30 R31 R32 R49 R70 R72 R73 R76 R78 R88 R91 R96 R98 R110: library part MCD-00053, "Resistor, 10K, 0402, +/-1%, 1/16W", Manufacturer=YAGEO, Manufacturer_Part_Number=RC0402FR-0710KL, Package=0402
R33 R34 R41: library part MCD-02455, "Resistor, 3K9, 0402, +/-1%, 1/16W, +/-100ppm/°C", Manufacturer=YAGEO, Manufacturer_Part_Number=RC0402FR-073K9L, Package=0402
R35: library part MCD-00409, "Resistor, 1K8, 0402, +/-1%, 1/16W", Manufacturer=YAGEO, Manufacturer_Part_Number=RC0402FR-071K8L, Package=0402
R36: library part MCD-00381, "Resistor, 1K3, 0402, +/-1%, 1/16W", Manufacturer=YAGEO, Manufacturer_Part_Number=RC0402FR-071K3L, Package=0402
R37: library part MCD-00513, "Resistor, 680K, 0402, +/-1%, 1/16W", Manufacturer=YAGEO, Manufacturer_Part_Number=RC0402FR-07680KL, Package=0402
R38: library part MCD-00483, "Resistor, 470K, 0402, +/-1%, 1/16W", Manufacturer=YAGEO, Manufacturer_Part_Number=RC0402FR-07470KL, Package=0402
R39 R115: library part MCD-00387, "Resistor, 1M3, 0402, +/-1%, 1/16W", Manufacturer=YAGEO, Manufacturer_Part_Number=RC0402FR-071M3L, Package=0402
R48: library part MCD-00373, "Resistor, 1K2, 0402, +/-1%, 1/16W", Manufacturer=YAGEO, Manufacturer_Part_Number=RC0402FR-071K2L, Package=0402
R51 R52 R53 R56 R57 R58 R63 R66 R67 R99 R106 R107 R108 R109: library part MCD-00056, "Resistor, 0R, 0603, +/-5%, 1/10W", Manufacturer=YAGEO, Manufacturer_Part_Number=RC0603JR-070RL, Package=0603
R54: library part MCD-02570, "Resistor, 15K, 0402, +/-0.1%, 1/16W, +/-25ppm/°C", Manufacturer=YAGEO, Manufacturer_Part_Number=RT0402BRD0715KL, Package=0402
R55: library part MCD-03683, "Resistor, 80K6, 0402, +/-0.1%, 1/16W, +/-25ppm/°C", Manufacturer=YAGEO, Manufacturer_Part_Number=RT0402BRD0780K6L, Package=0402
R60 R61 R62 R64 R65 R68: library part MCD-00181, "Resistor, 0R, 0603, +/- 0.5mR, 1/4W", Manufacturer="ROHM SEMICONDUCTOR", Manufacturer_Part_Number=PMR03EZPJ000, Package=0603
R69: library part MCD-00068, "Resistor, 1K5, 0402, +/-1%, 1/16W", Manufacturer=YAGEO, Manufacturer_Part_Number=RC0402FR-071K5L, Package=0402
R81: library part MCD-00723, "Resistor, 12K1, 0402, +/-1%, 1/16W", Manufacturer=YAGEO, Manufacturer_Part_Number=RC0402FR-0712K1L, Package=0402
R84 R85 R86 R87: library part MCD-00565, "Resistor, 49R9, 0402, +/-1%, 1/16W", Manufacturer=YAGEO, Manufacturer_Part_Number=RC0402FR-0749R9L, Package=0402
R89 R92 R93 R94: library part MCD-00515, "Resistor, 75R, 0402, +/-1%, 1/16W", Manufacturer=YAGEO, Manufacturer_Part_Number=RC0402FR-0775RL, Package=0402
R90: library part MCD-00433, "Resistor, 2K4, 0402, +/-1%, 1/16W", Manufacturer=YAGEO, Manufacturer_Part_Number=RC0402FR-072K4L, Package=0402
R95 R102: library part MCD-00441, "Resistor, 270R, 0402, +/-1%, 1/16W", Manufacturer=YAGEO, Manufacturer_Part_Number=RC0402FR-07270RL, Package=0402
R100: library part MCD-00511, "Resistor, 68K, 0402, +/-1%, 1/16W", Manufacturer=YAGEO, Manufacturer_Part_Number=RC0402FR-0768KL, Package=0402
R103: library part MCD-00223, "Resistor, 100K, 0603, +/- 1%, 1/10W", Manufacturer=YAGEO, Manufacturer_Part_Number=RC0603FR-07100KL, Package=0603
R104: library part MCD-00220, "Resistor, 10K, 0603, +/-1%, 1/10W", Manufacturer=YAGEO, Manufacturer_Part_Number=RC0603FR-0710KL, Package=0603
R111: library part MCD-00222, "Resistor, 47K, 0603, 1%, 1/10W", Manufacturer=YAGEO, Manufacturer_Part_Number=RC0603FR-0747KL, Package=0603
SB1 SB2 SB3 SB4 SB5: library part MCD-00071, "Solder Bridge ON", Manufacturer=YAGEO, Manufacturer_Part_Number=RC0603JR-070RL, Package=SB0603
SB6 SB7 SB8 SB9 SB11 SB12 SB13 SB15 SB16 SB17 SB18 SB19 SB20 SB21 SB22 SB23 SB24 SB25 SB26 SB27 SB28 SB29 SB30 SB31 SB32 SB33 SB34 SB35 SB36 SB37 SB38 SB39 SB40 SB43 SB44: library part MCD-00071, "Resistor, 0R, SB0603, 5%, 0.1W", Manufacturer=YAGEO, Manufacturer_HQ_COO=Unknown, Manufacturer_Part_Number=RC0603JR-070RL, Package=0603
SB10 SB14 SB45 SB46: library part MCD-01618, "Resistor, 0R, SB0402, 5%, 0.063W", Manufacturer=YAGEO, Manufacturer_Part_Number=RC0402JR-070RL, Package=0402
T1: library part MCD-01518, "Transistor, MOSFET, N-CH, 60V, 280mA, SOT23-3", Manufacturer="ON SEMICONDUCTOR", Manufacturer_Part_Number=NDS7002A, Package=SOT23-3
TP1 TP3 TP4 TP5 TP6 TP7 TP8 TP9 TP10 TP11 TP12 TP13 TP15 TP16 TP17 TP21 TP22 TP23 TP24 TP25 TP26 TP27 TP28 TP29 TP30 TP31 TP32 TP33 TP34 TP35 TP36 TP37 TP38 TP39 TP43 TP45 TP46 TP52 TP53 TP54 TP55 TP56 TP57 TP65 TP67 TP69 TP72: library part MCD-00631, "Test Point 0.6mm", Manufacturer=N/A, Manufacturer_HQ_COO=Unknown
TP2: library part MCD-00074, "Test Point 1mm", Manufacturer=N/A
TP41 TP42: library part MCD-01506, "Test Point trought hole 1mm/2mm", Manufacturer=N/A
U1: library part MCD-04286, "MCU, ARM Cortex-M33 32-bit, 4MB Flash, 1.5MB RAM, No Crypto", Manufacturer=STMICROELECTRONICS, Manufacturer_Part_Number=STM32H5E5ZJT6, Package=LQFP144
U2: library part MCD-03851, "MCU, ARM Cortex-M7 32-bit, 512KB Flash, 276KB RAM, With Crypto", Manufacturer=STMICROELECTRONICS, Manufacturer_Part_Number=STM32F723IEK6, Package=BGA-176
U3 U22: library part MCD-03060, "IC, ESD protection and Common Filter High Speed serial Interfaces, 10.7 GHz", Manufacturer=STMICROELECTRONICS, Package=uQFN-6
U4 U23: library part MCD-01207, "Diode, ESD TVS, 22V, 200nA, 25V8, QFN1610", Manufacturer=STMICROELECTRONICS, Manufacturer_HQ_COO=EU, Manufacturer_Part_Number=ESDA25P35-1U1M, Package=QFN1610
U5 U6 U9 U10 U12 U13 U14 U20 U24 U25 U26 U27 U28: library part MCD-03501, "Diode, ESD TVS, 5V5, 100nA, 10V, 0201", Manufacturer=STMICROELECTRONICS, Manufacturer_Part_Number=ESDZL5-1F4, Package=0201
U7: library part MCD-03814, "IC, eFuse with Overvoltage Protection 2V7 to 28V , 6V2 voltage clamp, 5A adjustable, 50mR", Manufacturer=LITTELFUSE, Package=DFN-8L
U8: library part MCD-02532, "IC, 2V7 to 18V, 4A, 34mR, eFuse with fast overvoltage protection", Manufacturer="TEXAS INSTRUMENTS", Package=WSON-8
U11: library part MCD-02514, "LDO, 300mA, 28V, Low-dropout voltage, with 5uA quiescent current", Manufacturer=STMICROELECTRONICS, Package=SOT23-5
U15: library part MCD-03923, "LDO, 3V3, 2A, Ultra low drop and low noise voltage regulator", Manufacturer=STMICROELECTRONICS, Package=DFN-6
U16: library part MCD-02219, "Regulator, 3A, DC step-down switching", Manufacturer=STMICROELECTRONICS, Manufacturer_HQ_COO=EU, Package=VFQFPN-8
U17: library part MCD-00719, "ETHERNET Transceiver, Small Footprint RMII, 10/100M, with HP Auto-MDIX and flexPWR technology", Manufacturer=MICROCHIP, Package=VQFN-24
U18: library part MCD-00250, "Very low capacitance ESD protection , 4 lines", Manufacturer=STMICROELECTRONICS, Manufacturer_HQ_COO=EU
U19: library part MCD-00718, "Discrete magnetic transformer module, 16 pins, SMT, 100 Base-TX", Manufacturer="DONGGUAN KEYOUDA ELECTRONIC TECHNOLOGY", Package=9.4x12.7x5.97mm
U21: library part MCD-01809, "IC, USB Type-C Overvoltage protection for VBUS and CC lines", Manufacturer=STMICROELECTRONICS, Manufacturer_HQ_COO=EU, Package=QFN-12
X1: library part MCD-01036, "Crystal, 24MHz, 6pF, +/-20ppm, 80R, 2x1.6mm", Manufacturer=NDK, Manufacturer_Part_Number=NX2016SA-24MHZ-EXS00A-CS10820, Package=2x1.6mm
X2: library part MCD-02291, "Crystal, 32.768kHz, 9pF, +/-20ppm, 70KR, 1.6x1mm", Manufacturer=NDK, Manufacturer_Part_Number=NX1610SE-32.768KHz-EXS00A-MU01499, Package=1.6x1mm
X3: library part MCD-02262, "Crystal, 48MHz, 7pF, +/-20 ppm, 80R, 1.6x1.2mm", Manufacturer=NDK, Manufacturer_Part_Number=NX1612SA-48MHZ-EXS00A-CS13734, Package=1.6x1.2mm
X4: library part MCD-01364, "Crystal, 25MHz, 6pF, +/-20ppm, 80R, 2x1.6mm", Manufacturer=NDK, Manufacturer_Part_Number=NX2016SA-25MHZ-EXS00A-CS11321, Package=2x1.6mm

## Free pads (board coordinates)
  round 0.508 on Mech16: 1(12.416,-22.77) 1(61.264,-22.77)
  round 3.2 hole 3.2 unplated: H1(10.866,105.42) H2(59.126,104.15) H3(43.886,53.35)

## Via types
v1: diameter 0.55, hole 0.35, Top Layer to Bottom Layer, tented both sides, 1373 vias

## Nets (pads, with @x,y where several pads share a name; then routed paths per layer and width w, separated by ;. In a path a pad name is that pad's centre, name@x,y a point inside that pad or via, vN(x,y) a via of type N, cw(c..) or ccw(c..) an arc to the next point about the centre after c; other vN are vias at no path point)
3V3: B1.3 B1.4 B3.2 B3.4 C37.2 C84.2 CN4.1 CN6.2 CN6.4 CN7.5 CN7.12 CN7.16 CN19.64 JP5.1 L4.1 LNK1.1 R17.2 R18.2 R19.2 R69.2 R70.2 R73.2 R76.2 R78.2 R88.1 R98.2 R99.1 R105.2 SB40.2 TP41.1 U15.1 U15.2 U17.9 U21.12 | length 72.3
  Top Layer w0.2: LNK1.1@32.35,114.05 v1(32.925,114.05)
  Top Layer w0.3: CN4.1@2.665,122.565 v1(2.665,123.64) ; v1@8.332,1.625 v1(8.4,1.625) R105.2@9.25,1.625 ; B3.4@14.8,103.675 B3.2@18.9,103.675 ; B1.4@23.95,106.15 v1(26.75,106.15) B1.3@29.55,106.15 ; U21.12@24.175,21.025 24.4,21.025 24.8,21.425 R88.1@25.725,21.425 v1(25.725,22.175) ; v1(30.95,34.075) R78.2@31.625,34.075 ; R69.2@32.875,39.4 R70.2@33.95,39.4 v1(33.95,40.075) ; U17.9@37.075,36.125 C84.2@37.075,38.5 v1(37.73,38.5) ; v1(37.9,12.525) R98.2@38.725,12.525 ; R73.2@38.475,39.4 38.57,39.4 38.675,39.505 38.675,39.55 v1(39.2,40.075) ; R76.2@41.775,39.4 v1(41.775,40.075) ; L4.1@42.575,29.675 42.825,29.925 v1(43.4,29.925) ; TP41.1@47.388,98.51 TP41.1@47.763,98.51 ; R17.2@51.775,123.275 v1(51.775,124) ; JP5.1@54.295,106.05 55.7,104.645 R99.1@55.7,103.775 ; R18.2@54.3,123.275 v1(54.3,124) ; R19.2@56.85,123.275 v1(56.85,124)
  Top Layer w0.4: v1(23.375,51) SB40.2@24.65,51
  Top Layer w1: CN7.12@5.786,88.91 CN6.2@10.866,88.91
  Signal Layer 3 w0.3: v1(30.95,34.075) 31.625,33.4 31.625,31.575 ; 33.125,31.675 41.65,31.675 v1(43.4,29.925)
  Signal Layer 3 w0.6: 22.4,105.65 22.9,106.15 v1(26.75,106.15) 34.775,106.15 35.5,106.875 35.5,109.925 32.925,112.5 v1(32.925,114.05)
  Bottom Layer w0.25: v1(43.65,48.075) CN19.64@43.65,49.35
  other v1: 1.375,69.51 2.125,69.51 1.375,70.26 2.125,70.26 1.375,84.75 2.125,84.75 1.375,85.5 2.125,85.5 49.263,98.99 50.013,98.99 49.263,99.74 50.013,99.74 16.85,103.675
3V3_Memory: C106.2 C107.2 CN19.2 CN19.4 CN19.72 CN19.74 SB40.1 | length 32.1
  Top Layer w0.4: SB40.1@25.775,51.025 v1(27.475,51.025)
  Signal Layer 3 w0.3: v1(27.475,51.025) 29.15,49.35 45.525,49.35 47.325,51.15 v1(48.125,51.15)
  Bottom Layer w0.3: v1(27.475,51.025) C107.2@28.2,51.025 28.15,50.975 28.15,50.275 ; CN19.2@28.15,49.35 28.15,50.275 ; CN19.4@28.65,49.35 28.65,50.175 28.474,50.351 28.226,50.351 28.15,50.275 ; CN19.72@45.65,49.35 45.65,49.924 CN19.74@46.15,49.924 ; CN19.74@46.15,49.35 CN19.74@46.15,49.924 ; v1(48.125,51.15) 48.1,51.125 C106.2@47.425,51.125 47.364,51.064 47.364,50.576 47.189,50.4 46.626,50.4 46.201,49.975 46.15,49.975 CN19.74@46.15,49.924
3V3_STLK: C5.1 C6.1 C8.1 C9.1 C13.1 C14.1 C15.1 C16.1 C18.1 C22.1 C25.1 C26.1 C27.1 C29.1 C30.1 C31.1 C32.1 C36.2 CN17.1 LD4.4 LD6.4 R28.2 R32.2 TP35.1 U2.C1 U2.C5 U2.C6 U2.C7 U2.C8 U2.C9 U2.F3 U2.G3 U2.G13 U2.H13 U2.J12 U2.J13 U2.K4 U2.N8 U2.N9 U2.N10 U2.P1 U2.R1 U11.1 | length 85.9
  Top Layer w0.2: v1@14.855,115.325 15.525,115.325 R28.2@15.525,115.225 R32.2@15.525,114.25 ; v1@16.425,116.77 C25.1@16.425,116.1 17.012,116.1 18.062,117.15 19.375,117.15 U2.C5@19.7,117.475 ; v1@16.425,119.07 C22.1@16.425,118.4 16.475,118.45 19.252,118.45 19.567,118.765 19.69,118.765 U2.C7@19.7,118.775 19.7,118.761 19.85,118.611 19.85,118.275 U2.C6@19.7,118.125 ; C15.1@16.425,121.175 16.425,120.688 18.013,119.1 19.375,119.1 U2.C8@19.7,119.425 ; C13.1@16.424,122.522 16.523,122.422 16.751,122.422 16.95,122.223 16.95,120.65 17.85,119.75 19.375,119.75 U2.C9@19.7,120.075 ; C27.1@18.525,113.15 C27.1@18.55,113.15 ; v1(19.175,113.15) 18.6,113.15 C27.1@18.55,113.15 ; U2.C1@19.7,114.875 19.375,114.55 19.045,114.55 18.006,113.511 18.006,113.426 17.905,113.325 17.905,113.3 17.75,113.145 C32.1@17.725,113.145 v1(17.075,113.145) 17.072,113.147 16.403,113.147 C26.1@16.4,113.15 16.5,113.25 16.5,113.5 16.672,113.673 17.278,113.673 17.805,114.2 18.185,114.2 18.725,114.74 18.725,115.01 18.915,115.2 19.835,115.2 20.025,115.39 20.025,115.66 20.215,115.85 20.485,115.85 20.675,116.04 20.675,116.224 20.675,116.31 20.865,116.5 21.325,116.5 U2.F3@21.65,116.175 ; v1@20.9,125.6 C5.1@21.525,125.6 21.525,124.804 21.975,124.354 21.975,123.19 21.975,123 U2.G13@22.3,122.675 ; U2.G3@22.3,116.175 21.975,115.85 20.865,115.85 20.675,115.66 20.675,114.669 20.156,114.15 19.292,114.15 18.705,113.563 18.705,113.422 18.705,113.305 C27.1@18.55,113.15 ; U2.H13@22.95,122.675 22.625,123 22.625,124.634 22.375,124.884 C6.1@22.375,125.6 v1@23,125.6 ; U2.J12@23.6,122.025 23.925,122.35 24.115,122.35 25.685,122.35 25.875,122.54 25.875,124.11 26.81,125.045 26.81,125.46 C9.1@26.95,125.6 26.962,125.612 27.588,125.612 v1(27.6,125.625) ; U2.J13@23.6,122.675 23.925,123 25.058,123 25.225,123.167 25.225,124.25 25.6,124.625 C8.1@25.6,125.6 v1@26.225,125.6 ; U2.K4@24.25,116.825 23.925,116.5 23.925,114.671 25.096,113.5 25.096,113.254 C29.1@25.2,113.15 v1@24.525,113.15 ; U2.N8@26.2,119.425 26.525,119.75 26.715,119.75 27.635,119.75 28.11,119.275 C18.1@29.1,119.275 ; U2.N9@26.2,120.075 26.537,120.412 26.703,120.412 26.715,120.4 27.945,120.4 28.17,120.625 C16.1@29.1,120.625 29.088,120.612 29.088,119.937 v1(29.075,119.925) ; U2.N10@26.2,120.725 26.525,121.05 27.799,121.05 28.174,121.425 C14.1@29.1,121.425 ; U2.P1@26.85,114.875 28.125,113.6 C31.1@28.125,113.15 28.131,113.156 28.806,113.156 v1(28.813,113.162) ; U2.R1@27.5,114.875 27.928,114.875 29.32,113.483 29.32,113.305 C30.1@29.475,113.15 ; v1@28.825,113.15 C30.1@29.475,113.15 ; C18.1@29.088,119.287 v1@29.088,119.913 ; C14.1@29.088,121.437 v1@29.088,122.063 ; C30.1@29.5,113.15 C30.1@29.475,113.15
  Top Layer w0.3: C13.1@16.421,122.525 16.424,122.522 16.424,121.851 v1(16.428,121.847) 16.426,121.846 16.426,121.176 C15.1@16.425,121.175 ; TP35.1@32.775,107.075 32.785,107.085 33.865,107.085 v1(33.875,107.095) ; v1(52.35,130.8) LD6.4@53.425,130.8 ; v1(57.55,130.8) LD4.4@58.625,130.8
  other v1: 34.625,107.095 33.875,107.845 34.625,107.845 24.513,113.162 14.853,115.328 16.428,116.772 16.428,119.072 29.075,122.075 20.887,125.588 23.013,125.612 26.238,125.612
5V: CN6.5 CN7.18 D2.1 JP1.2 JP1.4 JP1.6 JP1.8 R23.2 R48.2 R59.2 R60.1 TP38.1 | length 31.1
  Top Layer w0.2: v1(61.7,109) R48.2@62.375,109 62.375,106.75 TP38.1@61.875,106.25
  Top Layer w0.3: R59.2@10.875,94.825 10.9,94.8 11.8,94.8 v1(11.825,94.775) ; v1(29.475,116.75) R23.2@30.225,116.75
  Signal Layer 3 w0.5: JP1.8@66.745,114.715 JP1.6@66.745,117.255 JP1.4@66.745,119.795 JP1.2@66.745,122.335
  Bottom Layer w0.3: v1(29.475,116.75) 30.12,117.395 36.88,117.395 38.772,115.503 38.772,109.693 v1(40.17,108.295)
  other v1: 36.5,93.25 37.25,93.25 36.5,94 37.25,94 40.17,107.545 40.92,107.545 40.92,108.295
5V_EXT: CN7.6 JP1.5 | length 67
  Signal Layer 2 w2: CN7.6@5.786,96.53 10.875,96.53 ; 10.875,96.525 11.525,96.525 15.675,100.675 26.425,100.675 30.525,104.775 45.924,104.775 50.949,109.8 55,109.8 62.455,117.255 JP1.5@64.205,117.255
5V_STLK: C23.2 C24.2 CN10.8 JP1.1 R40.1 R42.1 TP26.1 U7.8 U8.5 U8.6 | length 3.5
  Top Layer w0.3: TP26.1@35.4,116.25 v1(36.375,116.25) ; R42.1@39.175,114.275 39.175,115.3 39.25,115.375 U8.5@39.25,115.475 ; U7.8@46.575,115.475 46.575,114.38 46.68,114.275 R40.1@46.725,114.275
  other v1: 48.75,115.475 49.5,115.475 36.375,115.5 37.125,115.5 48.75,116.225 49.5,116.225 37.125,116.25
5V_UCPD: JP1.7 Q1.1 Q1.2 Q1.3 R97.1 R100.2 R104.2 R115.1 U21.4 | length 21.6
  Top Layer w0.3: R104.2@12.3,11.059 v1(12.3,12) ; v1(13.525,10.225) R100.2@13.525,11.05 ; v1(19.025,22.6) Q1.1@19.025,23.375 Q1.1@19.025,23.4 ; v1(19.675,22.625) Q1.2@19.675,23.375 Q1.2@19.675,23.4 ; v1(20.325,22.625) Q1.3@20.325,23.375 Q1.3@20.325,23.4 ; R115.1@24.3,24.275 v1(24.3,25.025)
  Signal Layer 2 w0.35: v1(19.025,22.6) 19.037,22.612 19.663,22.612 v1(19.675,22.625) v1(20.325,22.625) ; v1(20.25,21.6) 20.25,21.654 20.325,21.729 v1(20.325,22.625) ; v1(24.3,25.025) 23.325,25.025 20.9,22.6 20.35,22.6 v1(20.325,22.625)
  Bottom Layer w2: 60.975,107.475 62.275,107.475 64.205,109.405 JP1.7@64.205,114.715
  other v1: 60.6,107.025 61.525,107.025 60.6,107.85 61.525,107.85
5V_VIN: C38.2 JP1.3 L2.2 R55.2 TP42.1 | length 4.2
  Top Layer w0.3: R55.2@23.7,100 25.5,100 26.5,99 v1(26.5,98)
  other v1: 26.5,97 27.5,97 27.5,98
AGND: C69.1 C70.1 C76.1 C77.1 CN10.32 SB19.2 U1.31 | length 33.5
  Top Layer w0.25: C76.1@40.775,57.225 C76.1@40.8,57.25 C69.1@40.8,58.125 40.93,58.255 40.93,58.504 41.175,58.749 v1(41.175,58.8) 41.175,58.881 41.375,59.081 41.375,60.15 U1.31@41.4,60.175 ; C70.1@43.45,57.25 C77.1@43.45,58.125 v1(43.45,58.85) ; 43.5,57.625 SB19.2@44.65,57.625 ; v1(54.8,61.7) 55.35,62.25 65.486,62.25 CN10.32@66.746,63.51
  Signal Layer 2 w0.25: v1(41.175,58.8) 42.1,58.8 42.15,58.85 v1(43.45,58.85) 44.95,58.85 47.075,60.975 54.075,60.975 v1(54.8,61.7)
BOOT0: B3.1 B3.3 CN7.7 R49.2 TP37.1 U1.138 U12.1 | length 81.3
  Top Layer w0.12: v1(4.5,107.45) 12.905,107.45 R49.2@13.505,106.85 ; R49.2@13.525,106.925 13.6,106.85 U12.1@14.806,106.85 ; U12.1@14.8,106.843 B3.3@14.8,105.275 15.075,105 18.625,105 B3.1@18.9,105.275 TP37.1@18.9,106.95 ; v1(23.1,65.75) 23.1,65.32 23.17,65.25 U1.138@24.325,65.25
  Signal Layer 2 w0.12: CN7.7@3.246,93.99 4.506,95.25 15.05,95.25 v1(19.75,90.55)
  Bottom Layer w0.12: CN7.7@3.246,93.99 1.8,95.436 1.8,102.925 4.5,105.625 v1(4.5,107.45) ; v1(19.75,90.55) 21.618,88.682 21.618,81.757 23.15,80.225 23.15,77.951 23.15,77.118 21.77,75.738 21.77,67.662 23.1,66.332 v1(23.1,65.75)
CON_USB_HS_N: CN13.A7 CN13.B7 U22.2 | length 12.5
  Top Layer w0.12: v1(18.57,7.11) cw(c17.846,6.386) 18.87,6.386 CN13.B7@18.87,6.195 ; CN13.A7@19.62,7.895 19.55,8.185 19.55,9.87 cw(c19.755,9.87) v1(19.755,10.075) 19.619,10.285 cw(c19.72,10.35) 19.6,10.35 19.6,11.09 cw(c19.62,11.09) U22.2@19.62,11.11
  Bottom Layer w0.12: v1(18.57,7.11) ccw(c18.57,7.385) 18.792,7.223 ccw(c18.695,7.293) 18.809,7.256 18.839,7.348 ccw(c18.725,7.385) 18.845,7.385 18.845,7.525 ccw(c18.59,7.525) 18.59,7.78 18.3,7.78 cw(c18.3,8.7) 17.38,8.7 17.38,10.3 cw(c18.375,10.3) 18.375,11.295 18.825,11.295 cw(c18.825,10.575) 19.545,10.575 19.545,10.285 ccw(c19.755,10.285) v1(19.755,10.075)
CON_USB_HS_P: CN13.A6 CN13.B6 U22.1 | length 11.7
  Top Layer w0.12: CN13.A6@19.12,7.895 19.21,8.185 19.281,8.267 ccw(c19.24,8.274) 19.282,8.274 19.304,9.856 ccw(c19.085,9.856) v1(19.085,10.075) ccw(c19.085,10.33) 19.34,10.33 19.34,10.74 ccw(c19.22,10.74) 19.26,10.853 U22.1@19.22,11.11 ; v1(19.24,7.11) cw(c18.926,6.796) 19.37,6.796 CN13.B6@19.37,6.195
  Bottom Layer w0.12: v1(19.085,10.075) ccw(c19.085,10.295) 19.305,10.295 19.305,10.575 ccw(c18.825,10.575) 18.825,11.055 18.375,11.055 ccw(c18.375,10.3) 17.62,10.3 17.62,8.7 ccw(c18.3,8.7) 18.3,8.02 18.59,8.02 cw(c18.59,7.525) 19.085,7.525 19.085,7.385 ccw(c19.205,7.385) 19.104,7.32 v1(19.24,7.11)
DBGIN.JTDI: CN4.8 CN7.17 R44.2 U1.110 U5.1 | length 89.4
  Top Layer w0.12: CN4.8@6.735,118.755 6.762,118.781 U5.1@8.8,118.781 v1(9.9,118.781) ; v1(13.85,109.9) 14.85,109.9 15.25,109.5 24.065,109.5 v1(26.095,111.53) ; v1(22.625,79.25) U1.110@24.325,79.25 ; v1@26.1,111.53 R44.2@26.1,112.25
  Signal Layer 2 w0.12: CN7.17@3.246,81.29 4.381,82.425 11.85,82.425 14.705,79.57 21.18,79.57 21.5,79.25 v1(22.625,79.25)
  Bottom Layer w0.12: v1(9.9,118.781) 10.994,118.781 13.075,116.7 13.1,116.675 13.1,111.253 13.1,110.65 v1(13.85,109.9) ; 18.14,85.496 18.14,84.178 21.9,80.418 22.201,80.418 22.625,79.993 v1(22.625,79.25) ; 18.15,85.496 18.15,95.857 18.14,95.867 18.14,96.206 17.435,96.911 17.435,102.134 26.095,110.794 v1(26.095,111.53)
DBGIN.MCO: C3.2 R7.2 SB5.2 TP2.1 | length 120.8
  Top Layer w0.12: R7.2@20.15,126.5 C3.2@20.15,127.475 v1(20.15,128.525) TP2.1@21.5,128.525 ; v1(34.85,53.275) 34.902,53.275 35.275,53.648 35.275,53.908 SB5.2@35.681,54.314
  Signal Layer 2 w0.12: v1(13.625,51.4) 16.223,51.4 16.588,51.765 25.908,51.765 26.843,52.7 28.05,52.7 28.4,53.05 32.875,53.05 33.1,53.275 v1(34.85,53.275)
  Bottom Layer w0.12: v1(13.625,51.4) 13.625,55.4 11.85,57.175 10.075,57.175 9.3,57.95 9.3,80.282 9.305,80.287 9.305,80.663 9.3,80.668 9.3,90.025 9.155,90.17 9.155,100.295 5.8,103.65 5.8,124.05 11.275,129.525 19.15,129.525 v1(20.15,128.525)
DBGIN.SWCLK: CN4.4 CN7.15 R15.2 U1.109 U20.1 | length 81.1
  Top Layer w0.12: CN4.4@6.735,121.295 6.747,121.306 U20.1@8.8,121.306 v1(9.9,121.306) ; v1@14.796,124.575 R15.2@15.521,124.575 ; v1(22.125,79.85) U1.109@24.325,79.85
  Signal Layer 2 w0.12: CN7.15@3.246,83.83 4.401,82.675 12.05,82.675 14.875,79.85 v1(22.125,79.85) ; v1(9.9,121.306) 10.631,121.306 13.905,124.58 v1(14.801,124.58)
  Bottom Layer w0.12: v1(14.801,124.58) 15.556,123.825 15.556,122.9 15.05,122.394 15.05,118.237 15.915,117.372 15.915,103.314 17.195,102.034 17.195,96.812 17.9,96.107 17.9,84.079 22.125,79.854 v1(22.125,79.85)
